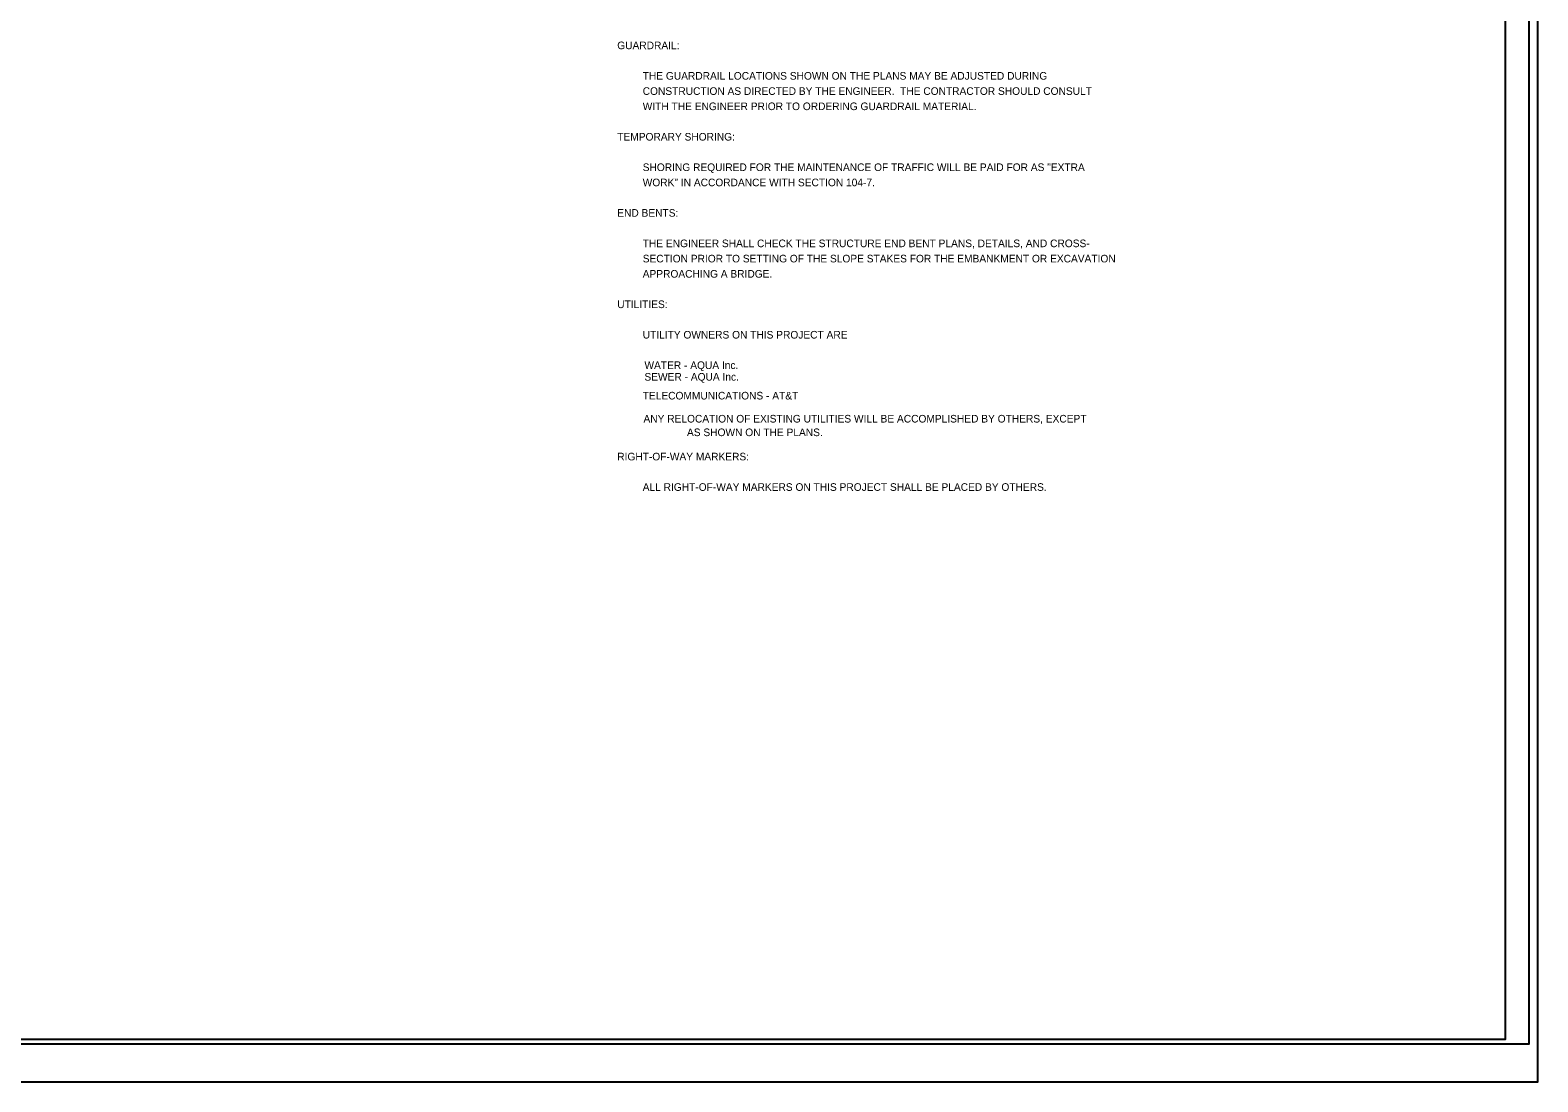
# Model space of a CAD drawing. Extents: x 9834 to 11517, y 9978 to 11072.
# Drawn here: x 10725 to 11517, y 9978 to 10530 of the extents above; entities that cross this region are included whole.
import ezdxf

# ---------------------------------------------------------------- set-up
doc = ezdxf.new("R2010")
doc.units = 0
for name, color, linetype in [('Default', 7, 'Continuous'), ('Sheet Cutting Line CELL', 7, 'Continuous'), ('Sheet Plan CELL', 7, 'Continuous'), ('Sheet Plot Border Inside CELL', 7, 'Continuous'), ('Sheet Plot Border Outside CELL', 7, 'Continuous')]:
    doc.layers.add(name, color=color, linetype=linetype)

msp = doc.modelspace()

# ---------------------------------------------------------------- linework, layer by layer
at = {"layer": 'Sheet Cutting Line CELL'}
msp.add_line((9833.5, 9977.5), (11517, 9977.5), dxfattribs=at)
at = {"layer": 'Sheet Plan CELL'}
msp.add_lwpolyline([(11500, 11050), (10000, 11050), (10000, 10000), (11500, 10000)], close=True, dxfattribs=at)
at = {"layer": 'Sheet Plot Border Inside CELL'}
msp.add_lwpolyline([(9846.5, 9997.5), (11512.5, 9997.5), (11512.5, 11052.5), (9846.5, 11052.5)], close=True, dxfattribs=at)
at = {"layer": 'Sheet Plot Border Outside CELL'}
msp.add_lwpolyline([(9833.5, 9977.5), (11517, 9977.5), (11517, 11072.5), (9833.5, 11072.5)], close=True, dxfattribs=at)

# ---------------------------------------------------------------- texts
at = {"layer": 'Default'}
for s, p in [('GUARDRAIL:  ', (11033.41, 10519.96)), ('         THE GUARDRAIL LOCATIONS SHOWN ON THE PLANS MAY BE ADJUSTED DURING ', (11033.41, 10503.96)), ('         CONSTRUCTION AS DIRECTED BY THE ENGINEER.  THE CONTRACTOR SHOULD CONSULT', (11033.41, 10495.96)), ('         WITH THE ENGINEER PRIOR TO ORDERING GUARDRAIL MATERIAL.', (11033.41, 10487.96)), ('TEMPORARY SHORING:  ', (11033.41, 10471.96)), ('         SHORING REQUIRED FOR THE MAINTENANCE OF TRAFFIC WILL BE PAID FOR AS "EXTRA ', (11033.41, 10455.96)), ('         WORK" IN ACCORDANCE WITH SECTION 104-7.  ', (11033.41, 10447.96)), ('END BENTS:  ', (11033.41, 10431.96)), ('         THE ENGINEER SHALL CHECK THE STRUCTURE END BENT PLANS, DETAILS, AND CROSS-', (11033.41, 10415.96)), ('         SECTION PRIOR TO SETTING OF THE SLOPE STAKES FOR THE EMBANKMENT OR EXCAVATION ', (11033.41, 10407.96)), ('         APPROACHING A BRIDGE.  ', (11033.41, 10399.96)), ('UTILITIES:  ', (11033.41, 10383.96)), ('         UTILITY OWNERS ON THIS PROJECT ARE  ', (11033.41, 10367.96)), ('         WATER - AQUA Inc.', (11034.32, 10351.96)), ('         SEWER - AQUA Inc.', (11034.32, 10345.85)), ('         TELECOMMUNICATIONS - AT&T', (11033.41, 10335.96)), ('         ANY RELOCATION OF EXISTING UTILITIES WILL BE ACCOMPLISHED BY OTHERS, EXCEPT', (11033.82, 10323.85)), ('AS SHOWN ON THE PLANS.', (11070.04, 10316.7)), ('RIGHT-OF-WAY MARKERS:  ', (11033.41, 10303.96)), ('         ALL RIGHT-OF-WAY MARKERS ON THIS PROJECT SHALL BE PLACED BY OTHERS.  ', (11033.41, 10287.96))]:
    msp.add_text(s, height=4, dxfattribs=at).set_placement(p)

doc.saveas('drawing.dxf')
